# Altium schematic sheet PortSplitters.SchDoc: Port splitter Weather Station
size A; Organization: Altium Limited; Address1: L3, 12a Rodborough Rd; Address2: Frenchs Forest; Address3: NSW; Address4: Australia 2086; DocumentNumber: 2; SheetNumber: 2; SheetTotal: 2
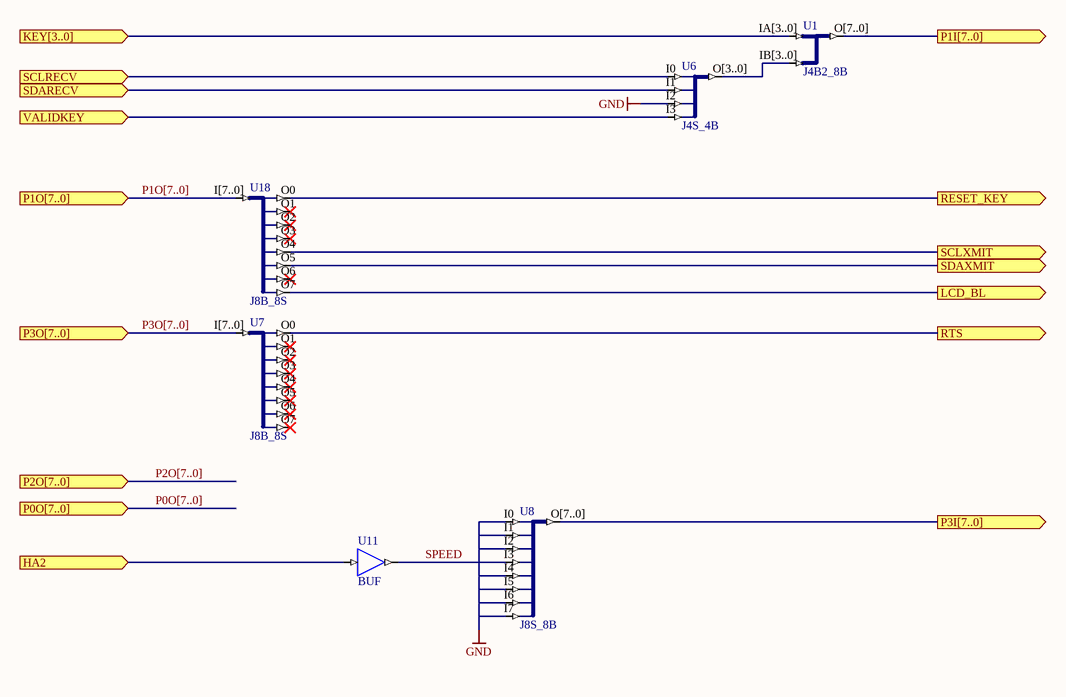
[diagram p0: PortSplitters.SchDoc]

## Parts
U1  J4B2_8B
U6  J4S_4B
U7  J8B_8S
U8  J8S_8B
U11  BUF
U18  J8B_8S

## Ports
HA2 (in), KEY[3..0] (in), LCD_BL (out), P0O[7..0] (in), P1I[7..0] (out), P1O[7..0] (in), P2O[7..0] (in), P3I[7..0] (out), P3O[7..0] (in), RESET_KEY (out), RTS (out), SCLRECV (in), SCLXMIT (out), SDARECV (in), SDAXMIT (out), VALIDKEY (in)

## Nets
GND: U6.I2 U8.I0 U8.I1 U8.I2 U8.I4 U8.I5 U8.I6 U8.I7
HA2: U11.I ; port HA2
LCD_BL: U18.O7 ; port LCD_BL
RESET_KEY: U18.O0 ; port RESET_KEY
RTS: U7.O0 ; port RTS
SCLRECV: U6.I0 ; port SCLRECV
SCLXMIT: U18.O4 ; port SCLXMIT
SDARECV: U6.I1 ; port SDARECV
SDAXMIT: U18.O5 ; port SDAXMIT
SPEED: U8.I3 U11.O
VALIDKEY: U6.I3 ; port VALIDKEY

Not connected (* = marked no-connect by the designer): U1 IA[3..0] IB[3..0] O[7..0]; U6 O[3..0]; U7 I[7..0] O1* O2* O3* O4* O5* O6* O7*; U8 O[7..0]; U18 I[7..0] O1* O2* O3* O6*

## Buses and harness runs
bus P0O[7..0] = port P0O[7..0]
bus P1O[7..0] = port P1O[7..0]
bus P2O[7..0] = port P2O[7..0]
bus P3O[7..0] = port P3O[7..0]

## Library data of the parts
U1 = J4B2_8B: 2 x 4-Bit input bus to 1 x 8-bit output bus; ArchiveName: GENERIC
U6 = J4S_4B: 4 Single pin inputs to single 4-Bit output bus; ArchiveName: GENERIC
U7 U18 = J8B_8S: 8-Bit input bus to 8 single pin outputs; ArchiveName: GENERIC
U8 = J8S_8B: 8 Single pin inputs to single 8-Bit output bus; ArchiveName: GENERIC
U11 = BUF: 1-bit General Purpose (Non-inverting) Buffer; ArchiveName: GENERIC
